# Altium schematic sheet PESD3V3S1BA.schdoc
size 127 x 101 mm
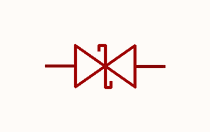
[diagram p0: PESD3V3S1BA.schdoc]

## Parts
D?  pesd3v3s1ba  [SOD-323_L1.7-W1.3-LS2.5-BI]  (value not drawn)

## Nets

Not connected (* = marked no-connect by the designer): D? 1(C) 2(A)

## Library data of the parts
D? = pesd3v3s1ba: Manufacturer: TECH PUBLIC(台舟); AddInBom: yes; ModelId: 3c4d3117213c44d8be2b8463c3660d20; ModelTransform: 98.425,51.181,0,0,0,0,-0.001,0.006,0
